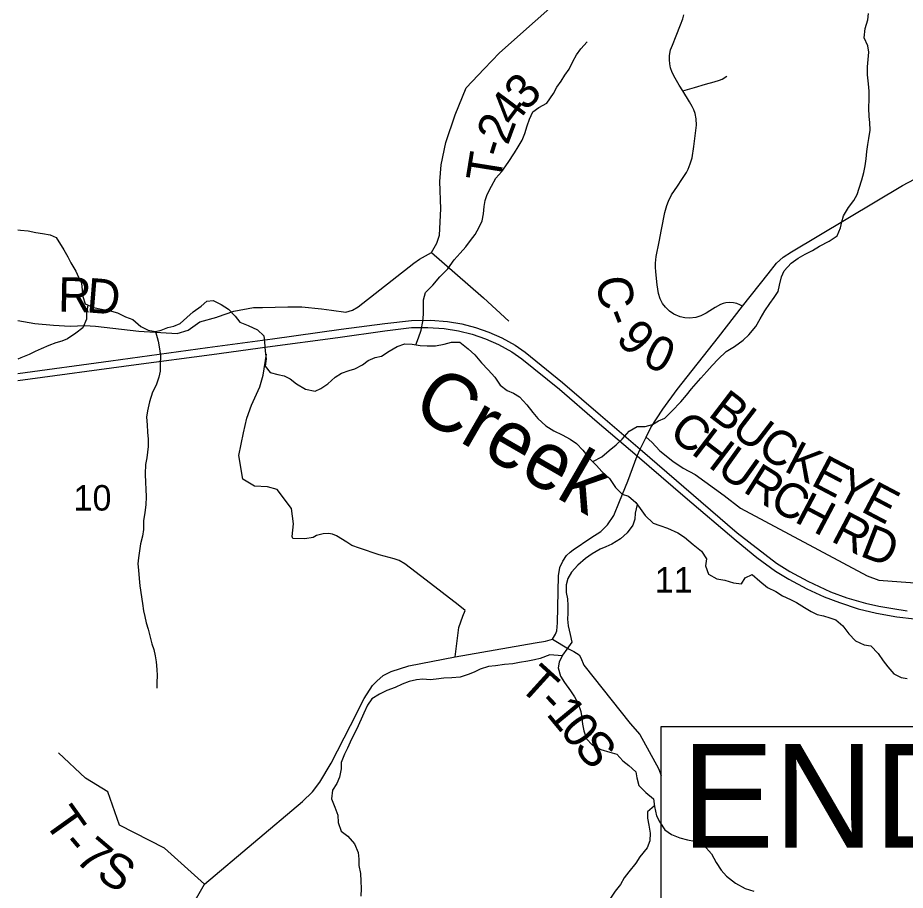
# Model space of a CAD drawing. Extents: x 0 to 34, y 0 to 22.
# Drawn here: x 2.1 to 3.557, y 18.109 to 19.541 of the extents above; entities that cross this region are included whole.
import ezdxf

# ---------------------------------------------------------------- set-up
doc = ezdxf.new("R2010")
doc.units = 0
for name, color, linetype in [('GM_X_County_Road', 7, 'Continuous'), ('GM_X_County_Road_Text', 7, 'Continuous'), ('GM_X_Minor_River', 7, 'Continuous'), ('GM_X_Minor_River_Text', 7, 'Continuous'), ('GM_X_Section_Text', 7, 'Continuous'), ('GM_X_State_Route', 7, 'Continuous'), ('GM_X_Township_Road', 7, 'Continuous'), ('GM_X_Township_Road_Text', 7, 'Continuous'), ('SH_Text', 7, 'Continuous')]:
    doc.layers.add(name, color=color, linetype=linetype)

msp = doc.modelspace()

# ---------------------------------------------------------------- linework, layer by layer
at = {"layer": 'GM_X_County_Road'}
msp.add_lwpolyline([(3.2902, 19.0674), (3.2854, 19.0699), (3.2808, 19.0718), (3.275, 19.0731), (3.2679, 19.0736), (3.2626, 19.073), (3.2584, 19.072), (3.254, 19.0704), (3.2452, 19.0654), (3.2364, 19.0598), (3.2304, 19.056), (3.2213, 19.0515), (3.2134, 19.0491), (3.2032, 19.048), (3.1952, 19.0485), (3.1878, 19.0501), (3.1771, 19.0547), (3.1699, 19.0595), (3.1634, 19.0658), (3.1586, 19.0722), (3.1548, 19.0794), (3.1519, 19.0881), (3.15, 19.1028), (3.1478, 19.1241), (3.1473, 19.1315), (3.1474, 19.1381), (3.1485, 19.1493), (3.1532, 19.1732), (3.1572, 19.1936), (3.1627, 19.2214), (3.1656, 19.2326), (3.1684, 19.2401), (3.1735, 19.2502), (3.1831, 19.2647), (3.1905, 19.2754), (3.198, 19.287), (3.2007, 19.2923), (3.2043, 19.3012), (3.2072, 19.3113), (3.21, 19.3295), (3.2129, 19.3516), (3.2144, 19.3649), (3.2141, 19.375), (3.2122, 19.3838), (3.2101, 19.3897), (3.2076, 19.3951), (3.2027, 19.4032), (3.1918, 19.4213), (3.1862, 19.4305), (3.1793, 19.442), (3.1744, 19.4512), (3.1718, 19.459), (3.1705, 19.4653), (3.17, 19.4718), (3.1703, 19.4792), (3.172, 19.4883), (3.1748, 19.4961), (3.181, 19.5116), (3.1881, 19.5292), (3.192, 19.5394), (3.1935, 19.546)], dxfattribs=at)
at = {"layer": 'GM_X_Minor_River'}
for points in [[(3.044, 18.8123), (3.0588, 18.8201), (3.071, 18.8307), (3.0824, 18.8401), (3.0923, 18.8491), (3.1041, 18.8623), (3.1171, 18.8702), (3.1299, 18.8701), (3.1421, 18.8735), (3.1519, 18.8795), (3.1622, 18.8839), (3.174, 18.8952), (3.1888, 18.9103), (3.198, 18.9216), (3.206, 18.9318), (3.2217, 18.9492), (3.2312, 18.9601), (3.2403, 18.9699), (3.2502, 18.9808), (3.2632, 18.9929), (3.2769, 19.0011), (3.2909, 19.0117), (3.3005, 19.0207), (3.3119, 19.0343), (3.3192, 19.0467), (3.3268, 19.06), (3.3349, 19.0721), (3.3418, 19.0819), (3.3483, 19.0917), (3.351, 19.1019), (3.3541, 19.1155), (3.3583, 19.1254), (3.3701, 19.1382), (3.3812, 19.1461), (3.3929, 19.1532), (3.4051, 19.1592), (3.4165, 19.166), (3.4321, 19.1742), (3.4454, 19.1832), (3.4511, 19.1961), (3.4531, 19.2059), (3.4558, 19.2161), (3.4642, 19.2297), (3.473, 19.2411), (3.478, 19.2509), (3.4815, 19.2615), (3.4861, 19.2747), (3.4892, 19.2872), (3.4912, 19.2978), (3.4928, 19.3096), (3.494, 19.3217), (3.4956, 19.3331), (3.4972, 19.3429), (3.4995, 19.3566), (3.4988, 19.3691), (3.4982, 19.3789), (3.4975, 19.3926), (3.498, 19.4078), (3.4981, 19.4203), (3.4966, 19.4328), (3.4952, 19.4472), (3.4953, 19.4605), (3.4961, 19.4723), (3.4974, 19.4848), (3.4955, 19.495), (3.49, 19.5083), (3.4912, 19.5235), (3.4958, 19.5375), (3.497, 19.5481)], [(2.7535, 19.0041), (2.7582, 19.0156), (2.7624, 19.0284), (2.7652, 19.0425), (2.766, 19.0542), (2.7662, 19.0781), (2.7697, 19.0902), (2.7815, 19.1023), (2.7929, 19.1155), (2.8059, 19.1287), (2.8166, 19.1438), (2.8265, 19.1547), (2.8357, 19.1652), (2.8433, 19.1751), (2.8509, 19.1852), (2.8578, 19.1973), (2.8624, 19.2079), (2.8648, 19.2189), (2.866, 19.231), (2.8676, 19.2409), (2.871, 19.2511), (2.8776, 19.2643), (2.8852, 19.2776), (2.8948, 19.2885), (2.9055, 19.3036), (2.9158, 19.3191), (2.9219, 19.3293), (2.9284, 19.3402), (2.9326, 19.3508), (2.9365, 19.3637), (2.94, 19.3743), (2.9458, 19.3868), (2.9556, 19.3939), (2.9689, 19.401), (2.9796, 19.4169), (2.985, 19.4271), (2.9923, 19.4369), (2.9984, 19.4467), (3.0056, 19.4565), (3.0114, 19.469), (3.0175, 19.48), (3.0248, 19.4898), (3.0351, 19.5015)], [(2.1, 19.1931), (2.1044, 19.1921), (2.1172, 19.1913), (2.1297, 19.1885), (2.1407, 19.1866), (2.1532, 19.1846), (2.1633, 19.1804), (2.1757, 19.1598), (2.182, 19.1484), (2.1869, 19.1385), (2.1955, 19.1248), (2.1996, 19.1149), (2.2048, 19.1054), (2.2059, 19.094), (2.2066, 19.0834), (2.2107, 19.0712), (2.2246, 19.0654), (2.2401, 19.0623), (2.2499, 19.0603), (2.2639, 19.0564), (2.2771, 19.0503), (2.2888, 19.0456), (2.302, 19.0342), (2.3144, 19.0284), (2.3261, 19.0257), (2.3356, 19.0279), (2.3462, 19.0327), (2.3561, 19.0349), (2.3667, 19.039), (2.3778, 19.0492), (2.388, 19.0582), (2.401, 19.0676), (2.4105, 19.0755), (2.4207, 19.077), (2.4339, 19.0705)], [(2.2148, 19.0695), (2.2128, 19.0556), (2.2128, 19.0461), (2.2066, 19.0322), (2.1952, 19.0231), (2.1819, 19.0141), (2.1724, 19.01), (2.1625, 19.0074), (2.1512, 19.0029), (2.1383, 18.9977), (2.1284, 18.9932), (2.1189, 18.9884), (2.1052, 18.9828), (2.1, 18.9806)], [(2.4339, 19.0705), (2.4463, 19.0624), (2.4572, 19.0513), (2.4647, 19.0414), (2.4783, 19.0356), (2.4934, 19.0287), (2.5039, 19.0188), (2.5054, 19.0082), (2.5064, 18.9937), (2.5078, 18.9812), (2.5062, 18.9691), (2.5145, 18.9584), (2.5273, 18.9553), (2.5375, 18.9533), (2.5473, 18.948), (2.5575, 18.9403), (2.5722, 18.9311), (2.5885, 18.928), (2.5979, 18.9324), (2.609, 18.9403), (2.6212, 18.9509), (2.6314, 18.9576), (2.6439, 18.9621), (2.6534, 18.9647), (2.6659, 18.9714), (2.6754, 18.9782), (2.6868, 18.9834), (2.6974, 18.9856), (2.71, 18.9935), (2.7229, 19.0014), (2.7358, 19.0055), (2.7475, 19.005), (2.7608, 19.003), (2.7725, 19.0022), (2.7861, 19.0025), (2.8001, 19.0051), (2.8123, 19.0084), (2.8259, 19.0083), (2.8398, 18.9976), (2.8507, 18.9876), (2.8616, 18.9743), (2.8725, 18.9629), (2.8834, 18.951), (2.892, 18.9377), (2.9037, 18.9293), (2.9139, 18.925), (2.9237, 18.9189), (2.9357, 18.9055), (2.9458, 18.893), (2.9537, 18.883), (2.9668, 18.8712), (2.9804, 18.8628), (2.994, 18.8566), (3.0068, 18.8493), (3.0173, 18.842), (3.0279, 18.831), (3.0388, 18.8176), (3.0504, 18.8058), (3.059, 18.7963), (3.0718, 18.7848), (3.0816, 18.7699), (3.0925, 18.7589), (3.1027, 18.7558), (3.1147, 18.7451), (3.1218, 18.7355), (3.1304, 18.7241), (3.1432, 18.7115), (3.1542, 18.7076), (3.167, 18.703), (3.184, 18.6957), (3.1945, 18.6884), (3.2088, 18.6762), (3.2227, 18.6655), (3.231, 18.6525), (3.229, 18.6415), (3.2342, 18.6278), (3.2478, 18.6202), (3.261, 18.6178), (3.2754, 18.6135), (3.2882, 18.6116), (3.2943, 18.6214), (3.3057, 18.627), (3.3185, 18.6163), (3.3309, 18.6056), (3.3449, 18.599), (3.3558, 18.5921), (3.3686, 18.586), (3.3785, 18.581), (3.392, 18.5729), (3.4026, 18.5664), (3.4127, 18.5611), (3.423, 18.5591), (3.4335, 18.556), (3.4433, 18.5525), (3.4546, 18.5426), (3.4644, 18.5296), (3.4756, 18.5182), (3.49, 18.5116), (3.5009, 18.51), (3.513, 18.4971), (3.5212, 18.4853)], [(2.3261, 19.0257), (2.3306, 19.0101), (2.3328, 18.9976), (2.3342, 18.9858), (2.3341, 18.9725), (2.3336, 18.9611), (2.3317, 18.9509), (2.327, 18.9377), (2.3213, 18.9263), (2.3163, 18.9104), (2.3128, 18.896), (2.3116, 18.8851), (2.3126, 18.8729), (2.3133, 18.8608), (2.314, 18.849), (2.3143, 18.8373), (2.3119, 18.8183), (2.3099, 18.8077), (2.309, 18.7925), (2.3097, 18.7774), (2.3104, 18.7679), (2.311, 18.7542), (2.3102, 18.7421), (2.3086, 18.7281), (2.3066, 18.7156), (2.3065, 18.7011), (2.3049, 18.6902), (2.3014, 18.6773), (2.2998, 18.6659), (2.2983, 18.6546), (2.2974, 18.6447), (2.2981, 18.6341), (2.2992, 18.6204), (2.3002, 18.6083), (2.3046, 18.5794), (2.3067, 18.5676), (2.3089, 18.5581), (2.3111, 18.5475), (2.3141, 18.5373), (2.3171, 18.5262), (2.3204, 18.5133), (2.3233, 18.5038), (2.3255, 18.4936), (2.327, 18.4837), (2.3284, 18.4712), (2.3291, 18.4613), (2.3286, 18.4499), (2.3282, 18.4404)], [(3.117, 18.742), (3.1138, 18.728), (3.113, 18.7181), (3.1099, 18.7079), (3.1004, 18.6955), (3.0897, 18.6857), (3.0756, 18.6771), (3.0658, 18.6726), (3.0563, 18.6685), (3.043, 18.661), (3.032, 18.6535), (3.0194, 18.6425), (3.0091, 18.6308), (3.0034, 18.6203), (3.0003, 18.61), (3.0005, 18.5975), (3.0024, 18.5873), (3.0034, 18.5763), (3.0033, 18.5634), (3.0029, 18.5539), (3.004, 18.5425), (3.0073, 18.5288), (3.0095, 18.5159), (3.0014, 18.5042), (2.9942, 18.4944), (2.9888, 18.4831), (2.9872, 18.4736), (2.9909, 18.4603), (2.9976, 18.4496), (3.0078, 18.4359), (3.0141, 18.426), (3.0194, 18.4165), (3.0246, 18.4024), (3.026, 18.3918), (3.0275, 18.3815), (3.0297, 18.3705), (3.0341, 18.3572), (3.0431, 18.3473), (3.0574, 18.34), (3.0722, 18.3354), (3.0835, 18.3319), (3.0933, 18.3212), (3.1034, 18.3135), (3.1147, 18.3032), (3.1165, 18.2933), (3.1199, 18.2808), (3.1311, 18.2694), (3.1439, 18.2587), (3.1457, 18.2461), (3.149, 18.2309), (3.1543, 18.2207), (3.1625, 18.2081), (3.1734, 18.2001), (3.187, 18.1947), (3.1995, 18.1915), (3.2112, 18.1892), (3.2263, 18.1826), (3.239, 18.1685), (3.2469, 18.1544), (3.2551, 18.1419), (3.2638, 18.1319), (3.2784, 18.1205), (3.2943, 18.1116), (3.3086, 18.1074)], [(2.9937, 18.4935), (2.9737, 18.4949), (2.9578, 18.4893), (2.9483, 18.4868), (2.9377, 18.4849), (2.9237, 18.4824), (2.9127, 18.4805), (2.8991, 18.4795), (2.8847, 18.4769), (2.873, 18.4759), (2.8593, 18.4718), (2.8494, 18.4669), (2.8396, 18.4628), (2.8263, 18.4587), (2.8127, 18.4573), (2.7994, 18.457), (2.7869, 18.4552), (2.7771, 18.4541), (2.765, 18.4554), (2.7547, 18.4543), (2.7426, 18.4513), (2.7312, 18.4472), (2.7195, 18.4416), (2.7062, 18.4364), (2.6937, 18.4308), (2.6815, 18.4229), (2.6742, 18.4123), (2.6685, 18.3995), (2.6639, 18.3897), (2.6562, 18.3726), (2.6508, 18.3624), (2.6458, 18.3519), (2.6416, 18.342), (2.6366, 18.3322), (2.6312, 18.3186), (2.6308, 18.308), (2.6284, 18.2943), (2.6238, 18.2841), (2.6169, 18.2728), (2.6149, 18.2588), (2.6205, 18.2451), (2.6257, 18.2321), (2.626, 18.22), (2.6312, 18.2059), (2.6421, 18.1975), (2.653, 18.1849), (2.659, 18.1709), (2.66, 18.1598), (2.66, 18.1492), (2.6625, 18.1363), (2.6632, 18.1238), (2.6639, 18.1117), (2.6634, 18.0988)], [(3.5212, 18.4853), (3.5287, 18.4757), (3.5385, 18.4639), (3.5505, 18.4581), (3.5604, 18.4562)], [(3.1456, 18.2471), (3.1339, 18.2375), (3.1342, 18.2269), (3.1364, 18.2155), (3.1386, 18.2026), (3.1378, 18.1897), (3.1332, 18.1783), (3.1213, 18.1636), (3.1148, 18.1534), (3.1034, 18.1391), (3.0957, 18.1289), (3.0896, 18.1183), (3.0808, 18.107), (3.072, 18.0938), (3.067, 18.0813), (3.0632, 18.0688), (3.0567, 18.0582), (3.0483, 18.0461), (3.0399, 18.036), (3.0368, 18.0261), (3.0333, 18.0144), (3.0313, 18.0011), (3.0312, 17.9878), (3.0304, 17.9724)]]:
    msp.add_lwpolyline(points, dxfattribs=at)
at = {"layer": 'GM_X_State_Route'}
for points in [[(3.1168, 18.8218), (3.1222, 18.8329), (3.1319, 18.8526), (3.1396, 18.8684), (3.1592, 18.8982), (3.1827, 18.9306), (3.2504, 19.0164), (3.2902, 19.0674), (3.3319, 19.1205), (3.3458, 19.138), (3.3568, 19.1482), (3.3706, 19.1569), (3.5526, 19.2656), (3.5826, 19.2813)], [(2.1, 18.9572), (2.2531, 18.9778), (2.4118, 18.9995), (2.5182, 19.0141), (2.6308, 19.0296), (2.7026, 19.0393), (2.7466, 19.0439), (2.7777, 19.0447), (2.8055, 19.0426), (2.8294, 19.0383), (2.8514, 19.0325), (2.8735, 19.0249), (2.8947, 19.0156), (2.9166, 19.0036), (2.9333, 18.9922), (2.9947, 18.9424), (3.0567, 18.8887), (3.1222, 18.8329), (3.2814, 18.6956), (3.3459, 18.6455), (3.3678, 18.6321), (3.397, 18.6162), (3.4347, 18.5988), (3.4611, 18.5889), (3.4922, 18.5802), (3.5137, 18.5749), (3.5366, 18.571), (3.5606, 18.5674)], [(2.1, 18.9455), (2.2946, 18.9717), (2.4186, 18.9884), (2.5103, 19.0008), (2.6256, 19.0162), (2.7025, 19.0268), (2.7466, 19.0323), (2.7734, 19.0328), (2.8001, 19.0308), (2.8239, 19.0272), (2.846, 19.0214), (2.868, 19.0139), (2.8892, 19.0045), (2.9111, 18.9925), (2.9279, 18.9811), (2.9893, 18.9313), (3.0513, 18.8776), (3.1168, 18.8218)], [(3.0073, 18.6636), (3.0118, 18.6674), (3.041, 18.6875), (3.0572, 18.6977), (3.0683, 18.7084), (3.0786, 18.7237), (3.088, 18.7468), (3.1016, 18.7801), (3.1168, 18.8218)], [(3.1168, 18.8218), (3.196, 18.754), (3.2798, 18.6828), (3.3133, 18.655), (3.3442, 18.6326), (3.3661, 18.6193), (3.3954, 18.6033), (3.424, 18.5903), (3.449, 18.5808), (3.48, 18.5709), (3.5099, 18.5635), (3.5436, 18.5574), (3.5726, 18.5541), (3.6063, 18.5528), (3.6415, 18.5532), (3.6711, 18.556), (3.6938, 18.5596), (3.7191, 18.5648), (3.7231, 18.5658), (3.7466, 18.5713)], [(2.3595, 18.0365), (2.4069, 18.1187), (2.5678, 18.2544), (2.5842, 18.2702), (2.5959, 18.2859), (2.6144, 18.3175), (2.6466, 18.379), (2.6687, 18.4233), (2.6824, 18.4447), (2.6896, 18.4519), (2.7001, 18.4612), (2.713, 18.4676), (2.7424, 18.4769), (2.8184, 18.4919), (2.9498, 18.5146), (2.9666, 18.5178), (2.9779, 18.5211), (2.983, 18.5293), (2.9849, 18.5348), (2.9864, 18.5476), (2.9878, 18.6249), (2.99, 18.6386), (2.9948, 18.6492), (3.0012, 18.6585), (3.0073, 18.6636)]]:
    msp.add_lwpolyline(points, dxfattribs=at)
at = {"layer": 'GM_X_Township_Road'}
for points in [[(2.7795, 19.1559), (2.788, 19.1708), (2.7923, 19.1841), (2.7944, 19.2276), (2.7931, 19.2721), (2.7952, 19.2996), (2.8028, 19.3363), (2.818, 19.3819), (2.8361, 19.4259), (2.8657, 19.4571), (2.891, 19.4833), (3.062, 19.6357), (3.1299, 19.694), (3.1446, 19.7065)], [(3.1918, 19.4213), (3.211, 19.4267), (3.2294, 19.4319), (3.2434, 19.4359), (3.252, 19.4385), (3.2564, 19.4403), (3.2644, 19.4449)], [(2.1, 19.0441), (2.128, 19.0393), (2.1588, 19.0361), (2.1861, 19.035), (2.21, 19.0358), (2.2278, 19.0347), (2.2986, 19.0266), (2.3619, 19.0226), (2.3798, 19.0283), (2.3988, 19.0416), (2.427, 19.0497), (2.4282, 19.0502), (2.4549, 19.0591), (2.4869, 19.0655), (2.5018, 19.0655), (2.5436, 19.0667), (2.5662, 19.0663), (2.5986, 19.0633), (2.6153, 19.0608), (2.6387, 19.0578), (2.6494, 19.0608), (2.6588, 19.0667), (2.7501, 19.138), (2.7595, 19.1448), (2.7795, 19.1559), (2.7962, 19.141), (2.8648, 19.0812), (2.9062, 19.0428)], [(2.8184, 18.4919), (2.8241, 18.5402), (2.8306, 18.5585), (2.8344, 18.5682), (2.8233, 18.5772), (2.7707, 18.6177), (2.7357, 18.6444), (2.7261, 18.6502), (2.7178, 18.653), (2.6932, 18.6592), (2.6612, 18.6704), (2.6484, 18.6746), (2.6402, 18.68), (2.6232, 18.6907), (2.6168, 18.6935), (2.6101, 18.6944), (2.6013, 18.6937), (2.5905, 18.6909), (2.5852, 18.688), (2.5715, 18.6858), (2.5518, 18.6862), (2.5506, 18.6894), (2.5526, 18.7103), (2.5494, 18.7353), (2.5258, 18.7664), (2.5103, 18.771), (2.4887, 18.7722), (2.4698, 18.7837), (2.4632, 18.8225), (2.4705, 18.8596), (2.4763, 18.8839), (2.4836, 18.9048), (2.4974, 18.9354), (2.5032, 18.9544), (2.5084, 18.9885)], [(3.1319, 18.8526), (3.1413, 18.8445), (3.1541, 18.83), (3.1754, 18.8133), (3.1925, 18.8018), (3.2121, 18.7911), (3.2599, 18.7566), (3.2868, 18.7357), (3.4949, 18.625), (3.5138, 18.618), (3.5355, 18.6159), (3.7447, 18.601)], [(2.9779, 18.5211), (3.0044, 18.505), (3.0132, 18.5008), (3.0219, 18.4949), (3.0245, 18.4904), (3.0294, 18.4781), (3.1054, 18.3824), (3.1213, 18.3641), (3.1521, 18.3086), (3.1565, 18.2971)], [(2.4069, 18.1187), (2.3409, 18.1775), (2.2668, 18.2154), (2.248, 18.2702), (2.2112, 18.2925), (2.1668, 18.3343)]]:
    msp.add_lwpolyline(points, dxfattribs=at)
at = {"layer": 'SH_Text'}
msp.add_lwpolyline([(3.1565, 18.3776), (4.9408, 18.3776), (4.9408, 17.6129), (3.1565, 17.6129)], close=True, dxfattribs=at)

# ---------------------------------------------------------------- texts
at = {"layer": 'GM_X_County_Road_Text'}
for s, rotation, p in [('C', 278.1085, (3.0497, 19.1134)), ('-', 291.4996, (3.0599, 19.0536)), ('9', 312.3492, (3.0803, 19.013)), ('0', 334.7184, (3.123, 18.973))]:
    msp.add_text(s, height=0.0568, rotation=rotation, dxfattribs=at).set_placement(p)
at = {"layer": 'GM_X_Minor_River_Text'}
msp.add_text('Creek', height=0.0947, rotation=329.9966, dxfattribs=at).set_placement((2.7437, 18.892))
at = {"layer": 'GM_X_Section_Text'}
for s, p in [('10', (2.1916, 18.732)), ('11', (3.1461, 18.5974))]:
    msp.add_text(s, height=0.04186, rotation=0, dxfattribs=at).set_placement(p)
at = {"layer": 'GM_X_Township_Road_Text'}
for s, rotation, p in [('3', 46.5273, (2.9346, 19.3862)), ('4', 53.2602, (2.9148, 19.3595)), ('2', 69.687, (2.9047, 19.3304)), ('-', 72.8783, (2.8981, 19.3089)), ('T', 80.8632, (2.8918, 19.269)), ('R', 358.8993, (2.1658, 19.0585)), ('D', 355.3943, (2.2116, 19.0576)), ('B', 322.5478, (3.2315, 18.8886)), ('U', 322.5458, (3.2686, 18.8602)), ('C', 322.6063, (3.1665, 18.8549)), ('H', 322.6965, (3.2037, 18.8265)), ('C', 325.9994, (3.3113, 18.8276)), ('K', 332.5557, (3.3561, 18.7979)), ('U', 324.4333, (3.245, 18.7951)), ('E', 332.2409, (3.4004, 18.7749)), ('R', 327.914, (3.2888, 18.7639)), ('Y', 332.2408, (3.438, 18.7551)), ('C', 331.2523, (3.3314, 18.7373)), ('E', 332.2409, (3.4822, 18.7318)), ('H', 332.1546, (3.3732, 18.7144)), ('R', 332.2926, (3.433, 18.6828)), ('D', 338.7941, (3.4808, 18.6582)), ('T', 317.792, (2.9203, 18.4418)), ('-', 313.1175, (2.951, 18.4141)), ('1', 309.5571, (2.9663, 18.3978)), ('0', 308.6281, (2.9884, 18.371)), ('S', 310.2024, (3.0114, 18.3423)), ('T', 305.472, (2.1415, 18.2212)), ('-', 310.193, (2.1693, 18.1826)), ('7', 319.6351, (2.1916, 18.1575)), ('S', 329.0772, (2.2266, 18.1289))]:
    msp.add_text(s, height=0.0568, rotation=rotation, dxfattribs=at).set_placement(p)
at = {"layer": 'SH_Text'}
msp.add_text('END PROJECT', height=0.17, dxfattribs=at).set_placement((3.1899, 18.1788))

doc.saveas('drawing.dxf')
